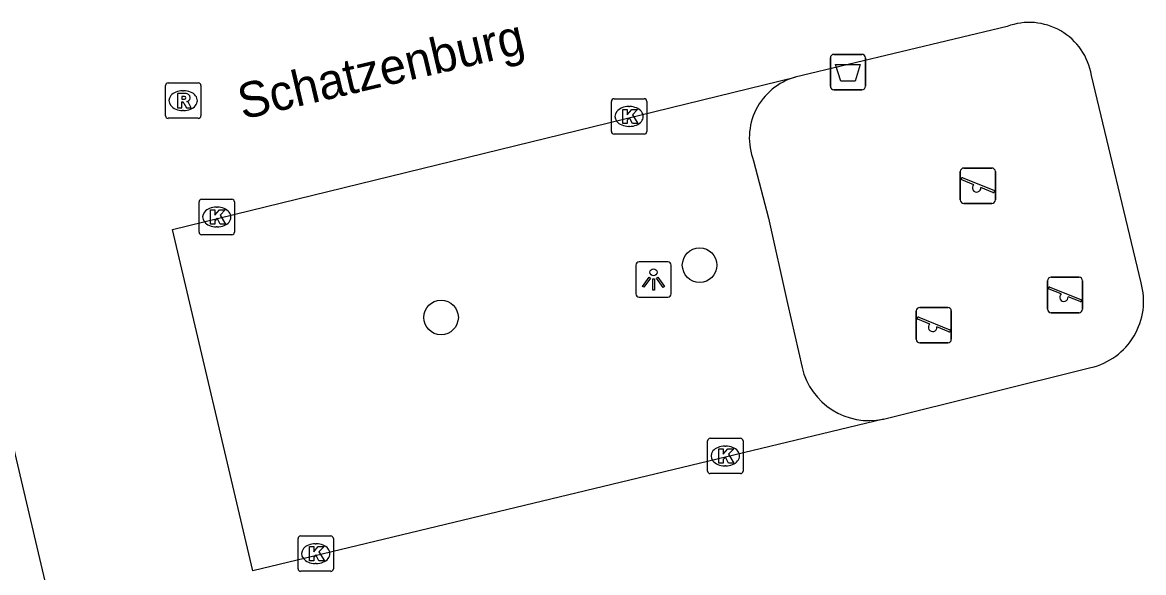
# Model space of a CAD drawing. Extents: x 158038 to 159242, y 380133 to 381214.
# Drawn here: x 158641.12 to 158672.8, y 380595.35 to 380610.89 of the extents above; entities that cross this region are included whole.
import ezdxf

# ---------------------------------------------------------------- set-up
doc = ezdxf.new("R2010")
doc.units = 0
for name, color, linetype in [('IMGEO_Afvalbak', 7, 'Continuous'), ('IMGEO_Boom', 7, 'Continuous'), ('IMGEO_Hek', 7, 'Continuous'), ('IMGEO_Kolk', 7, 'Continuous'), ('IMGEO_Lichtpunt', 7, 'Continuous'), ('IMGEO_Openbare_ruimte_label', 7, 'Continuous'), ('IMGEO_Parkeervlak_open', 7, 'Continuous'), ('IMGEO_Rijbaan_lokaal_open', 7, 'Continuous'), ('IMGEO_Rioolput', 7, 'Continuous'), ('IMGEO_Speelvoorziening', 7, 'Continuous')]:
    doc.layers.add(name, color=color, linetype=linetype)

msp = doc.modelspace()

# ---------------------------------------------------------------- linework, layer by layer
at = {"layer": 'IMGEO_Afvalbak'}
for p, q in [((158663.95, 380609.091), (158663.95, 380609.891)), ((158663.95, 380609.891), (158663.95, 380609.091)), ((158664.05, 380609.991), (158664.84, 380609.991)), ((158664.84, 380609.991), (158664.05, 380609.991)), ((158664.94, 380609.891), (158664.94, 380609.091)), ((158664.94, 380609.091), (158664.94, 380609.891)), ((158664.84, 380608.991), (158664.05, 380608.991)), ((158664.05, 380608.991), (158664.84, 380608.991))]:
    msp.add_line(p, q, dxfattribs=at)
msp.add_lwpolyline([(158664.093, 380609.705), (158664.797, 380609.705), (158664.648, 380609.235), (158664.242, 380609.235), (158664.093, 380609.705)], dxfattribs=at)
for centre, start, end in [((158664.05, 380609.891), 90, 180), ((158664.05, 380609.891), 90, 180), ((158664.84, 380609.891), 0, 90), ((158664.84, 380609.891), 360, 90), ((158664.05, 380609.091), 180, 270), ((158664.05, 380609.091), 180, 270), ((158664.84, 380609.091), 270, 0), ((158664.84, 380609.091), 270, 0)]:
    msp.add_arc(centre, 0.1, start, end, dxfattribs=at)
at = {"layer": 'IMGEO_Boom'}
for centre in [(158660.256, 380604.036), (158652.948, 380602.56)]:
    msp.add_circle(centre, 0.489, dxfattribs=at)
at = {"layer": 'IMGEO_Hek'}
for points in [[(158668.944, 380610.78), (158662.959, 380609.345)], [(158672.732, 380603.538), (158671.327, 380609.397)], [(158661.782, 380606.987), (158662.205, 380605.36)], [(158662.738, 380602.954), (158663.15, 380601.146)], [(158665.451, 380599.684), (158671.311, 380601.141)]]:
    msp.add_lwpolyline(points, dxfattribs=at)
for centre, radius, start, end in [((158669.568, 380609.111), 1.782, 9.2328, 110.5088), ((158663.437, 380607.634), 1.777, 105.5994, 201.3483), ((158670.871, 380603.022), 1.932, 283.1787, 15.5003), ((158665.054, 380601.602), 1.958, 193.4531, 281.6851)]:
    msp.add_arc(centre, radius, start, end, dxfattribs=at)
at = {"layer": 'IMGEO_Kolk'}
for p, q in [((158657.763, 380607.811), (158657.763, 380608.663)), ((158657.838, 380608.737), (158658.69, 380608.737)), ((158658.251, 380608.517), (158658.276, 380608.517)), ((158658.764, 380608.663), (158658.764, 380607.811)), ((158658.274, 380607.957), (158658.249, 380607.957)), ((158658.69, 380607.737), (158657.838, 380607.737)), ((158646.11, 380604.97), (158646.11, 380605.822)), ((158646.185, 380605.896), (158647.037, 380605.896)), ((158646.598, 380605.676), (158646.623, 380605.676)), ((158647.111, 380605.822), (158647.111, 380604.97)), ((158646.621, 380605.116), (158646.596, 380605.116)), ((158647.037, 380604.896), (158646.185, 380604.896)), ((158660.481, 380598.221), (158660.481, 380599.073)), ((158660.556, 380599.147), (158661.408, 380599.147)), ((158661.482, 380599.073), (158661.482, 380598.221)), ((158660.969, 380598.927), (158660.994, 380598.927)), ((158660.992, 380598.367), (158660.967, 380598.367)), ((158661.408, 380598.147), (158660.556, 380598.147)), ((158648.906, 380595.462), (158648.906, 380596.314)), ((158648.981, 380596.388), (158649.833, 380596.388)), ((158649.394, 380596.168), (158649.419, 380596.168)), ((158649.907, 380596.314), (158649.907, 380595.462)), ((158649.417, 380595.608), (158649.392, 380595.608)), ((158649.833, 380595.388), (158648.981, 380595.388))]:
    msp.add_line(p, q, dxfattribs=at)
for points in [[(158657.763, 380607.811), (158657.763, 380608.663)], [(158657.838, 380608.737), (158658.69, 380608.737)], [(158658.764, 380608.663), (158658.764, 380607.811)], [(158658.084, 380608.437), (158658.207, 380608.437), (158658.207, 380608.286), (158658.337, 380608.437), (158658.501, 380608.437), (158658.355, 380608.286), (158658.508, 380608.037), (158658.356, 380608.037), (158658.271, 380608.201), (158658.207, 380608.134), (158658.207, 380608.037), (158658.084, 380608.037), (158658.084, 380608.437)], [(158658.69, 380607.737), (158657.838, 380607.737)], [(158646.11, 380604.97), (158646.11, 380605.822)], [(158646.185, 380605.896), (158647.037, 380605.896)], [(158647.111, 380605.822), (158647.111, 380604.97)], [(158646.431, 380605.596), (158646.554, 380605.596), (158646.554, 380605.445), (158646.684, 380605.596), (158646.848, 380605.596), (158646.702, 380605.445), (158646.855, 380605.196), (158646.703, 380605.196), (158646.618, 380605.36), (158646.554, 380605.293), (158646.554, 380605.196), (158646.431, 380605.196), (158646.431, 380605.596)], [(158647.037, 380604.896), (158646.185, 380604.896)], [(158660.481, 380598.221), (158660.481, 380599.073)], [(158660.556, 380599.147), (158661.408, 380599.147)], [(158661.482, 380599.073), (158661.482, 380598.221)], [(158660.802, 380598.847), (158660.925, 380598.847), (158660.925, 380598.696), (158661.055, 380598.847), (158661.219, 380598.847), (158661.073, 380598.696), (158661.226, 380598.447), (158661.074, 380598.447), (158660.989, 380598.611), (158660.925, 380598.544), (158660.925, 380598.447), (158660.802, 380598.447), (158660.802, 380598.847)], [(158661.408, 380598.147), (158660.556, 380598.147)], [(158648.906, 380595.462), (158648.906, 380596.314)], [(158648.981, 380596.388), (158649.833, 380596.388)], [(158649.907, 380596.314), (158649.907, 380595.462)], [(158649.227, 380596.088), (158649.35, 380596.088), (158649.35, 380595.937), (158649.48, 380596.088), (158649.644, 380596.088), (158649.498, 380595.937), (158649.651, 380595.688), (158649.499, 380595.688), (158649.414, 380595.852), (158649.35, 380595.785), (158649.35, 380595.688), (158649.227, 380595.688), (158649.227, 380596.088)], [(158649.833, 380595.388), (158648.981, 380595.388)]]:
    msp.add_lwpolyline(points, dxfattribs=at)
for centre, start, end in [((158657.84, 380608.661), 91.552, 178.448), ((158657.84, 380608.661), 91.552, 178.448), ((158658.688, 380608.661), 1.552, 88.448), ((158658.688, 380608.661), 1.552, 88.448), ((158657.84, 380607.813), 181.552, 268.448), ((158657.84, 380607.813), 181.552, 268.448), ((158658.688, 380607.813), 271.552, 358.448), ((158658.688, 380607.813), 271.552, 358.448), ((158646.187, 380605.82), 91.552, 178.448), ((158646.187, 380605.82), 91.552, 178.448), ((158647.035, 380605.82), 1.552, 88.448), ((158647.035, 380605.82), 1.552, 88.448), ((158646.187, 380604.972), 181.552, 268.448), ((158646.187, 380604.972), 181.552, 268.448), ((158647.035, 380604.972), 271.552, 358.448), ((158647.035, 380604.972), 271.552, 358.448), ((158660.558, 380599.071), 91.552, 178.448), ((158660.558, 380599.071), 91.552, 178.448), ((158661.406, 380599.071), 1.552, 88.448), ((158661.406, 380599.071), 1.552, 88.448), ((158660.558, 380598.223), 181.552, 268.448), ((158660.558, 380598.223), 181.552, 268.448), ((158661.406, 380598.223), 271.552, 358.448), ((158661.406, 380598.223), 271.552, 358.448), ((158648.983, 380596.312), 91.552, 178.448), ((158648.983, 380596.312), 91.552, 178.448), ((158649.831, 380596.312), 1.552, 88.448), ((158649.831, 380596.312), 1.552, 88.448), ((158648.983, 380595.464), 181.552, 268.448), ((158648.983, 380595.464), 181.552, 268.448), ((158649.831, 380595.464), 271.552, 358.448), ((158649.831, 380595.464), 271.552, 358.448)]:
    msp.add_arc(centre, 0.0765, start, end, dxfattribs=at)
for centre, major_axis, ratio, start_param, end_param in [((158658.25, 380608.237), (-0.387, 0.002), 0.722429, 4.712389, 7.853982), ((158658.275, 380608.237), (-0.39, 0.002), 0.717154, 1.570796, 4.712389), ((158646.597, 380605.396), (-0.387, 0.002), 0.722429, 4.712389, 7.853982), ((158646.622, 380605.396), (-0.39, 0.002), 0.717154, 1.570796, 4.712389), ((158660.968, 380598.647), (-0.387, 0.002), 0.722429, 4.712389, 7.853982), ((158660.993, 380598.647), (-0.39, 0.002), 0.717154, 1.570796, 4.712389), ((158649.393, 380595.888), (-0.387, 0.002), 0.722429, 4.712389, 7.853982), ((158649.418, 380595.888), (-0.39, 0.002), 0.717154, 1.570796, 4.712389)]:
    msp.add_ellipse(centre, major_axis=major_axis, ratio=ratio, start_param=start_param, end_param=end_param, dxfattribs=at)
at = {"layer": 'IMGEO_Lichtpunt'}
for p, q in [((158658.453, 380604.037), (158658.453, 380603.23)), ((158658.453, 380604.037), (158658.453, 380603.23)), ((158659.355, 380604.132), (158658.547, 380604.132)), ((158659.355, 380604.132), (158658.547, 380604.132)), ((158659.449, 380603.23), (158659.449, 380604.037)), ((158659.449, 380603.23), (158659.449, 380604.037)), ((158658.547, 380603.136), (158659.355, 380603.136)), ((158658.547, 380603.136), (158659.355, 380603.136))]:
    msp.add_line(p, q, dxfattribs=at)
for points in [[(158658.827, 380603.701), (158658.866, 380603.673), (158658.678, 380603.411), (158658.64, 380603.438), (158658.827, 380603.701)], [(158659.039, 380603.673), (158659.077, 380603.7), (158659.264, 380603.438), (158659.225, 380603.41), (158659.039, 380603.673)], [(158658.929, 380603.653), (158658.976, 380603.653), (158658.976, 380603.331), (158658.929, 380603.331), (158658.929, 380603.653)]]:
    msp.add_lwpolyline(points, dxfattribs=at)
msp.add_circle((158658.952, 380603.835), 0.0994, dxfattribs=at)
for centre, start, end in [((158658.547, 380604.037), 90, 180), ((158658.547, 380604.037), 90, 180), ((158659.355, 380604.037), 0, 90), ((158659.355, 380604.037), 0, 90), ((158658.547, 380603.23), 180, 270), ((158658.547, 380603.23), 180, 270), ((158659.355, 380603.23), 270, 0), ((158659.355, 380603.23), 270, 360)]:
    msp.add_arc(centre, 0.0946, start, end, dxfattribs=at)
at = {"layer": 'IMGEO_Parkeervlak_open'}
msp.add_lwpolyline([(158661.782, 380606.987), (158662.205, 380605.36), (158662.738, 380602.954), (158663.15, 380601.146)], dxfattribs=at)
for centre, radius, start, end in [((158663.437, 380607.634), 1.777, 105.5994, 201.3483), ((158665.054, 380601.602), 1.958, 193.4531, 281.6851)]:
    msp.add_arc(centre, radius, start, end, dxfattribs=at)
at = {"layer": 'IMGEO_Rijbaan_lokaal_open'}
for points in [[(158668.944, 380610.78), (158662.959, 380609.345)], [(158638.238, 380610.014), (158643.37, 380588.22)], [(158665.451, 380599.684), (158647.633, 380595.402), (158645.363, 380605.047), (158662.959, 380609.345)], [(158672.732, 380603.538), (158671.327, 380609.397)], [(158665.451, 380599.684), (158671.311, 380601.141)]]:
    msp.add_lwpolyline(points, dxfattribs=at)
for centre, radius, start, end in [((158669.568, 380609.111), 1.782, 9.2328, 110.5088), ((158670.871, 380603.022), 1.932, 283.1787, 15.5003)]:
    msp.add_arc(centre, radius, start, end, dxfattribs=at)
at = {"layer": 'IMGEO_Rioolput'}
for p, q in [((158645.16, 380608.258), (158645.16, 380609.11)), ((158645.235, 380609.184), (158646.087, 380609.184)), ((158646.161, 380609.11), (158646.161, 380608.258)), ((158645.648, 380608.964), (158645.673, 380608.964)), ((158646.087, 380608.184), (158645.235, 380608.184)), ((158645.671, 380608.404), (158645.646, 380608.404))]:
    msp.add_line(p, q, dxfattribs=at)
for points in [[(158645.16, 380608.258), (158645.16, 380609.11)], [(158645.235, 380609.184), (158646.087, 380609.184)], [(158646.161, 380609.11), (158646.161, 380608.258)], [(158645.749, 380608.882), (158645.497, 380608.884), (158645.497, 380608.484)], [(158645.675, 380608.803), (158645.621, 380608.803), (158645.621, 380608.722)], [(158645.497, 380608.484), (158645.621, 380608.484), (158645.621, 380608.646), (158645.632, 380608.646)], [(158645.621, 380608.722), (158645.673, 380608.722)], [(158645.679, 380608.617), (158645.75, 380608.484), (158645.89, 380608.484), (158645.825, 380608.61)], [(158646.087, 380608.184), (158645.235, 380608.184)]]:
    msp.add_lwpolyline(points, dxfattribs=at)
for centre, radius, start, end in [((158645.237, 380609.108), 0.0765, 91.552, 178.448), ((158645.237, 380609.108), 0.0765, 91.552, 178.448), ((158646.085, 380609.108), 0.0765, 1.552, 88.448), ((158646.085, 380609.108), 0.0765, 1.552, 88.448), ((158645.681, 380608.707), 0.0964, 77.0061, 93.1865), ((158645.695, 380608.764), 0.0378, 276.6634, 79.6772), ((158645.748, 380608.772), 0.109, 350.3612, 89.416), ((158645.631, 380608.593), 0.0533, 26.0293, 88.6989), ((158645.657, 380608.911), 0.19, 274.7715, 282.9687), ((158645.746, 380608.772), 0.112, 277.5842, 350.9817), ((158645.73, 380608.557), 0.108, 29.5134, 73.7905), ((158645.237, 380608.26), 0.0765, 181.552, 268.448), ((158645.237, 380608.26), 0.0765, 181.552, 268.448), ((158646.085, 380608.26), 0.0765, 271.552, 358.448), ((158646.085, 380608.26), 0.0765, 271.552, 358.448)]:
    msp.add_arc(centre, radius, start, end, dxfattribs=at)
for centre, major_axis, ratio, start_param, end_param in [((158645.647, 380608.684), (-0.387, 0.002), 0.722429, 4.712389, 7.853982), ((158645.672, 380608.684), (-0.39, 0.002), 0.717154, 1.570796, 4.712389)]:
    msp.add_ellipse(centre, major_axis=major_axis, ratio=ratio, start_param=start_param, end_param=end_param, dxfattribs=at)
at = {"layer": 'IMGEO_Speelvoorziening'}
for p, q in [((158667.623, 380605.88), (158667.623, 380606.68)), ((158667.623, 380606.68), (158667.623, 380605.88)), ((158667.723, 380606.78), (158668.513, 380606.78)), ((158668.513, 380606.78), (158667.723, 380606.78)), ((158668.613, 380606.68), (158668.613, 380605.88)), ((158668.613, 380605.88), (158668.613, 380606.68)), ((158668.006, 380606.308), (158667.667, 380606.445)), ((158667.692, 380606.505), (158668.568, 380606.152)), ((158668.544, 380606.092), (158668.204, 380606.229)), ((158668.513, 380605.78), (158667.723, 380605.78)), ((158667.723, 380605.78), (158668.513, 380605.78)), ((158670.088, 380602.794), (158670.088, 380603.594)), ((158670.088, 380603.594), (158670.088, 380602.794)), ((158670.157, 380603.419), (158671.033, 380603.066)), ((158670.188, 380603.694), (158670.978, 380603.694)), ((158670.978, 380603.694), (158670.188, 380603.694)), ((158671.078, 380603.594), (158671.078, 380602.794)), ((158671.078, 380602.794), (158671.078, 380603.594)), ((158670.471, 380603.222), (158670.132, 380603.359)), ((158671.009, 380603.006), (158670.669, 380603.143)), ((158666.478, 380602.842), (158667.268, 380602.842)), ((158667.268, 380602.842), (158666.478, 380602.842)), ((158666.378, 380601.942), (158666.378, 380602.742)), ((158666.378, 380602.742), (158666.378, 380601.942)), ((158666.761, 380602.37), (158666.422, 380602.507)), ((158666.447, 380602.567), (158667.323, 380602.214)), ((158667.368, 380602.742), (158667.368, 380601.942)), ((158667.368, 380601.942), (158667.368, 380602.742)), ((158670.978, 380602.694), (158670.188, 380602.694)), ((158670.188, 380602.694), (158670.978, 380602.694)), ((158667.299, 380602.154), (158666.959, 380602.291)), ((158667.268, 380601.842), (158666.478, 380601.842)), ((158666.478, 380601.842), (158667.268, 380601.842))]:
    msp.add_line(p, q, dxfattribs=at)
for centre, radius, start, end in [((158667.723, 380606.68), 0.1, 90, 180), ((158667.723, 380606.68), 0.1, 90, 180), ((158668.513, 380606.68), 0.1, 0, 90), ((158668.513, 380606.68), 0.1, 360, 90), ((158667.68, 380606.475), 0.0327, 68.078, 248.078), ((158668.085, 380606.218), 0.12, 130.9928, 5.1632), ((158668.556, 380606.122), 0.0327, 248.078, 68.078), ((158667.723, 380605.88), 0.1, 180, 270), ((158667.723, 380605.88), 0.1, 180, 270), ((158668.513, 380605.88), 0.1, 270, 0), ((158668.513, 380605.88), 0.1, 270, 0), ((158670.188, 380603.594), 0.1, 90, 180), ((158670.188, 380603.594), 0.1, 90, 180), ((158670.145, 380603.389), 0.0327, 68.078, 248.078), ((158670.978, 380603.594), 0.1, 0, 90), ((158670.978, 380603.594), 0.1, 360, 90), ((158670.55, 380603.132), 0.12, 130.9928, 5.1632), ((158671.021, 380603.036), 0.0327, 248.078, 68.078), ((158666.478, 380602.742), 0.1, 90, 180), ((158666.478, 380602.742), 0.1, 90, 180), ((158667.268, 380602.742), 0.1, 0, 90), ((158667.268, 380602.742), 0.1, 360, 90), ((158670.188, 380602.794), 0.1, 180, 270), ((158670.188, 380602.794), 0.1, 180, 270), ((158670.978, 380602.794), 0.1, 270, 0), ((158670.978, 380602.794), 0.1, 270, 0), ((158666.435, 380602.537), 0.0327, 68.078, 248.078), ((158666.84, 380602.28), 0.12, 130.9928, 5.1632), ((158667.311, 380602.184), 0.0327, 248.078, 68.078), ((158666.478, 380601.942), 0.1, 180, 270), ((158666.478, 380601.942), 0.1, 180, 270), ((158667.268, 380601.942), 0.1, 270, 0), ((158667.268, 380601.942), 0.1, 270, 0)]:
    msp.add_arc(centre, radius, start, end, dxfattribs=at)

# ---------------------------------------------------------------- texts
at = {"layer": 'IMGEO_Openbare_ruimte_label'}
msp.add_text('Schatzenburg', height=1, rotation=13.2438, dxfattribs=at).set_placement((158647.341, 380608.146))

doc.saveas('drawing.dxf')
